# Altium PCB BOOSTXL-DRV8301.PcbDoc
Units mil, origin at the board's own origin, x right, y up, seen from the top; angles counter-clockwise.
Board outline 2200 x 2300 mil, 2 copper layers (Top, Bottom), stack 61.9 mil thick; 114 components, 81 nets, 348 pads, 370 vias.
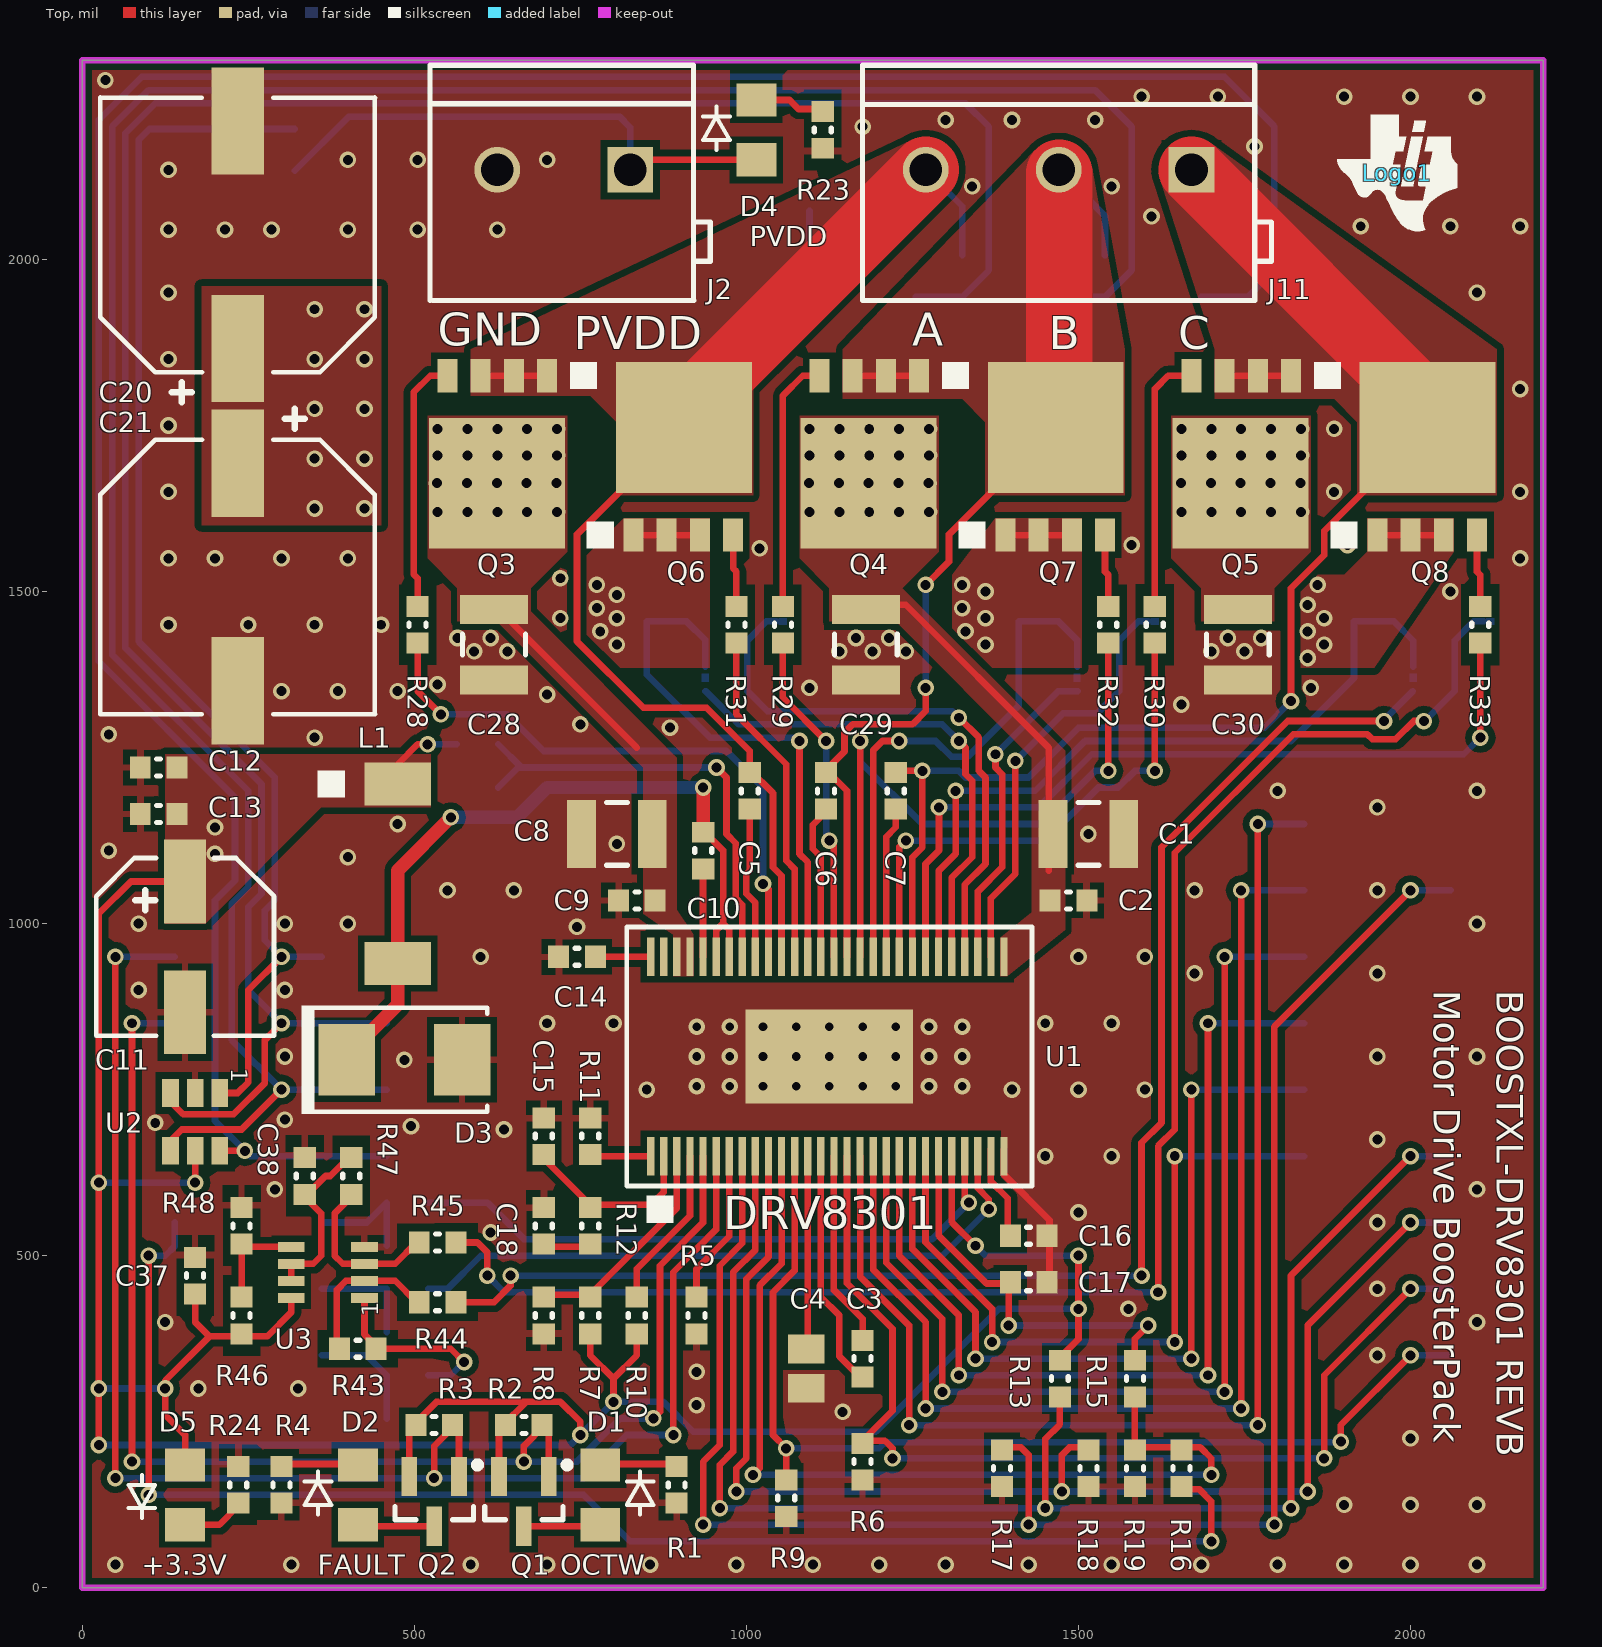
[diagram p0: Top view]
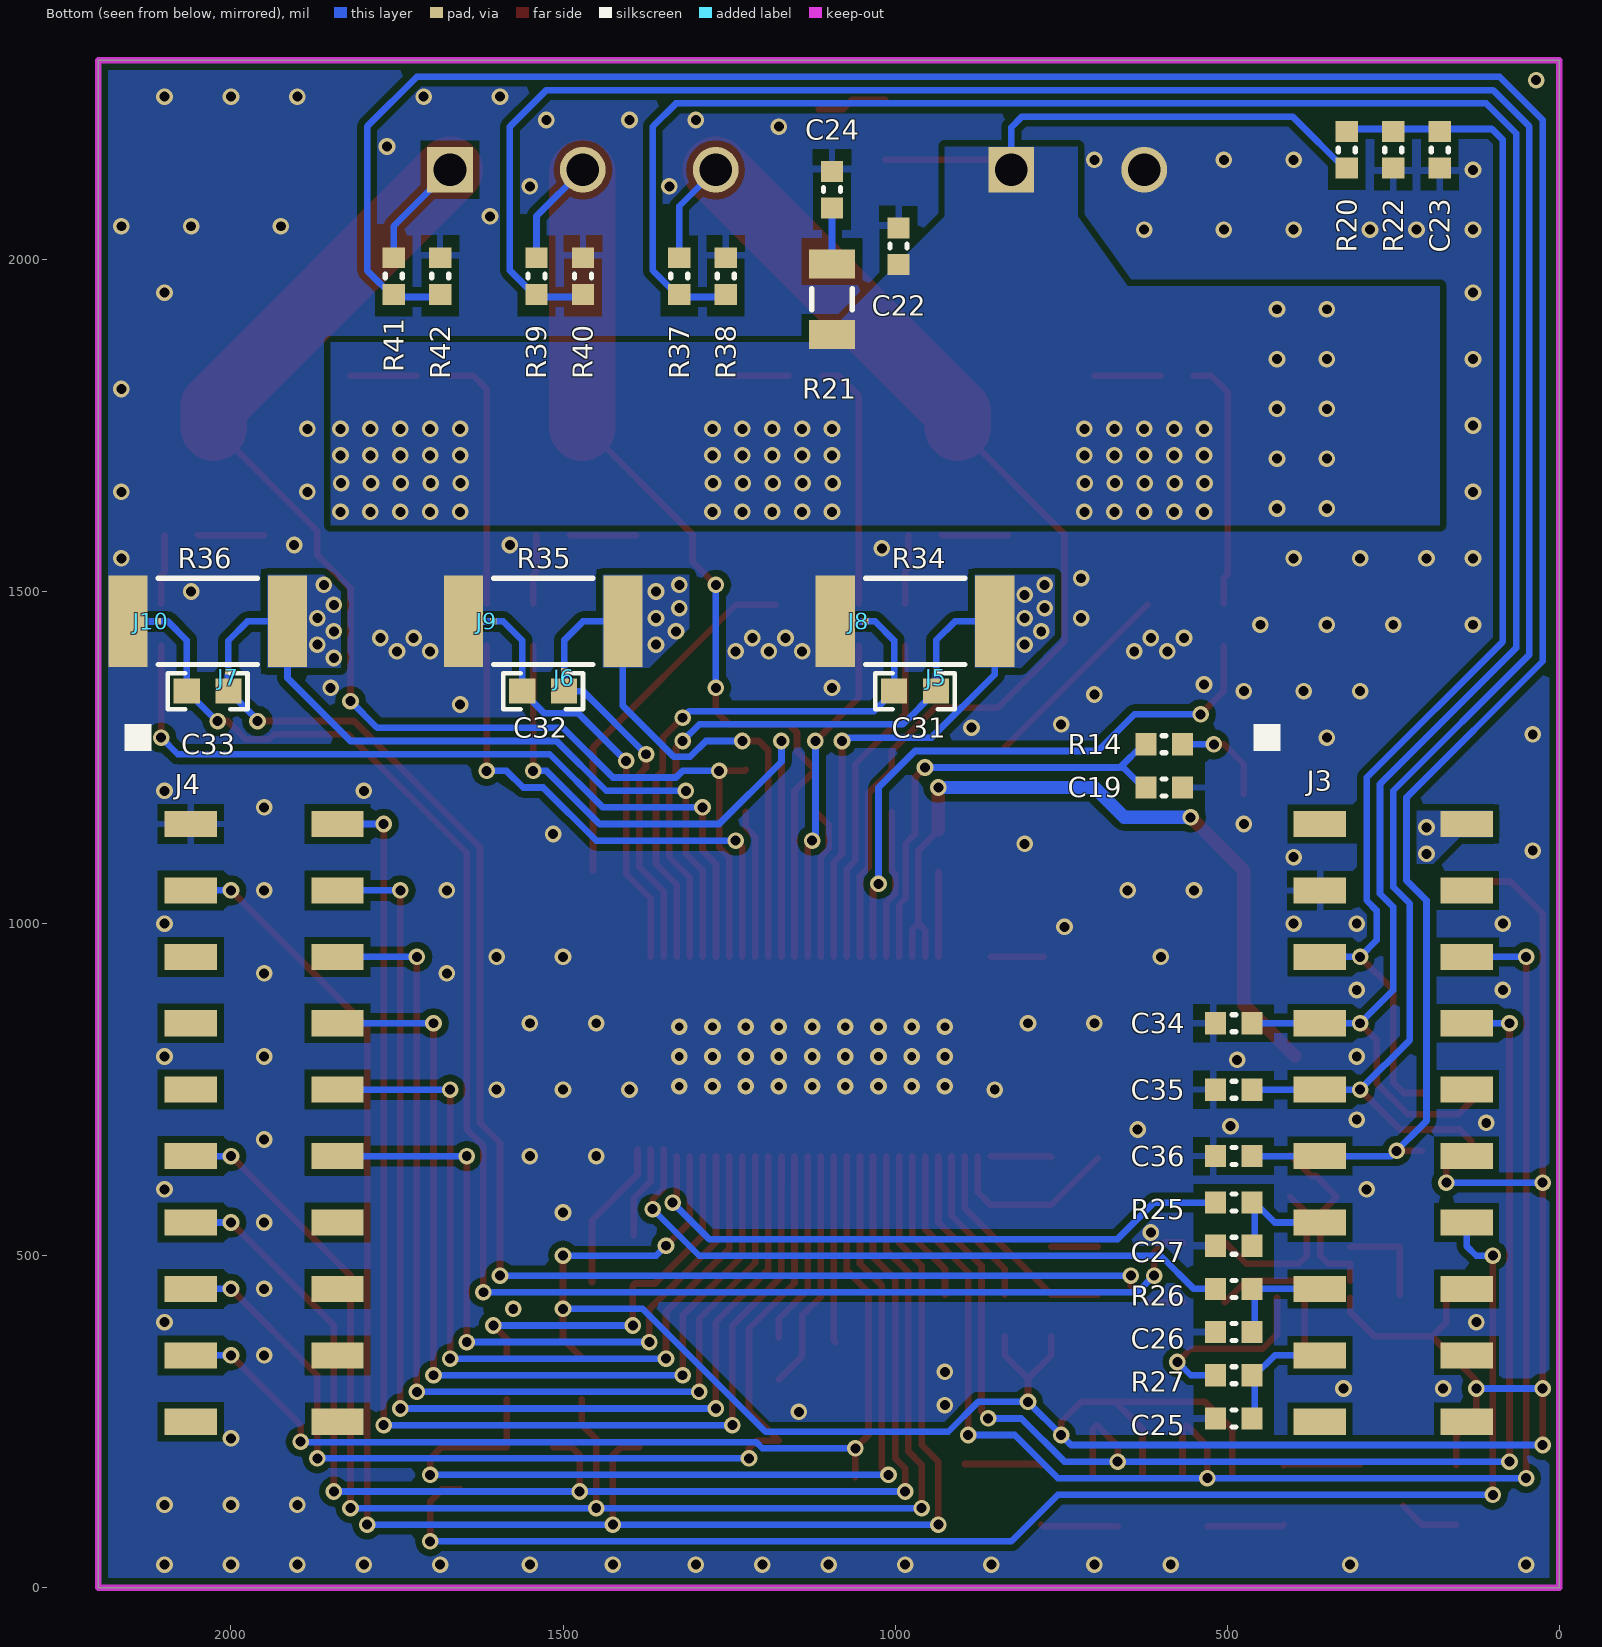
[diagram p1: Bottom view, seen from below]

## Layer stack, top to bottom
Top: signal copper 1.35
Dielectric: core 59.2, FR-4, Dk 4.3
Bottom: signal copper 1.35

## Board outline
0,0 0,2300 2200,2300 2200,0

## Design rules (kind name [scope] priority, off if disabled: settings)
Clearance Clearance_Poly_GND [InNamedPolygon('GND_TOP') or InNamedPolygon('GND_BOT')] p1: gap=10
Clearance "'Default' PADS rule_18" [All] p2: gap=6
Clearance "'Default' PADS rule_15" [IsVia vs IsVia] p3: gap=6
ComponentClearance "'Default' PADS rule_12" [All] p1: gap=0 collisioncheckmode=3 verticalgap=0 showdistances=FALSE
DiffPairsRouting [All] p1: maxlimit=10 minlimit=10 mostfreqgap=10 maxuncoupledlength=500
FlightTimeFalling "'Default' PADS rule_10" [All] p1: maximum=10.00
FlightTimeRising "'Default' PADS rule_9" [All] p1: maximum=10.00
MaxMinImpedance "'Default' PADS rule_8" [All] p1: minimum=50.00 maximum=150.0
MinimumSolderMaskSliver [All] p1: minsoldermaskwidth=4
PlaneClearance "'Default' PADS rule_14" [All] p1: clearance=15
PolygonConnect PolygonConnect_1 [IsNamedPolygon('GND_Top') or IsNamedPolygon('GND_Bot') vs Not (InComponent('U1') or InComponent('J2') or InComponent('J11') or InComponent('J1') or InComponent('J5') or InComponent('J6') or InComponent('J7') or InComponent('J8') or InComponent('J9') or InComponent('J10') or InComponent('C1') or InComponent('C4') or InComponent('C8') or InComponent('C16') or InComponent('C17') or InComponent('C20') or InComponent('C21') or InComponent('C28') or InComponent('C29') or InComponent('C30') or InComponent('R34') or InComponent('R35') or InComponent('R36') or IsStitchingVia or IsVia)] p1: connectstyle=Relief reliefconductorwidth=10 reliefentries=4 polygonreliefangle="90 Angle" airgapwidth=10
PolygonConnect [All] p2: connectstyle=Direct reliefconductorwidth=10 reliefentries=4 polygonreliefangle="90 Angle" airgapwidth=10
RoutingLayers "'Default' PADS rule_3" [All] p1: top layer_v5=TRUE bottom layer_v5=TRUE
RoutingPriority "'Default' PADS rule_2" [All] p1: routingpriority=3
RoutingTopology "'Default' PADS rule" [All] p1: topology=Shortest
RoutingVias "'Default' PADS rule_4" [All] p1: holewidth=15 width=25 viastyle="Through Hole" minholewidth=10 minwidth=15 maxholewidth=25 maxwidth=60
SMDToCorner "'Default' PADS rule_16" [All] p1: distance=0
SMDToPlane "'Default' PADS rule_17" [All] p1: distance=80000
SilkToSilkClearance [All] p1: silktosilkclearance=5
SilkscreenOverComponentPads [All] p1: minsilkscreentomaskgap=3
SolderMaskExpansion "Solder Mask Expansion from CAM settings" [All] p1: expansion=2
Width "'Default' PADS rule_13" [All] p1: maxlimit=150 minlimit=10 preferedwidth=10
19 further rules are at their usual default settings.

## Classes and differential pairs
component class DRV8301: C1 C2 C3 C4 C5 C6 C7 C8 C9 C10 C11 C12 C13 C14 C15 C16 C17 C18 C19 D1 D2 D3 L1 Logo1 Q1 Q2 R1 R2 R3 R4 R5 R6 R7 R8 R9 R10 R11 R12 R13 R14 R15 R16 R17 R18 R19 U1
component class LAUNCHPAD: C20 C21 C22 C23 C24 C25 C26 C27 D4 D5 J2 J3 J4 R20 R21 R22 R23 R24 R25 R26 R27 U2
component class MOTOR: C28 C29 C30 C31 C32 C33 J5 J6 J7 J8 J9 J10 J11 Q3 Q4 Q5 Q6 Q7 Q8 R28 R29 R30 R31 R32 R33 R34 R35 R36
component class SENSE: C34 C35 C36 C37 C38 R37 R38 R39 R40 R41 R42 R43 R44 R45 R46 R47 R48 U3
differential pair C_ISENSE: +C_ISENSE_P -C_ISENSE_N
differential pair A_ISENSE: +A_ISENSE_P -A_ISENSE_N
differential pair B_ISENSE: +B_ISENSE_P -B_ISENSE_N

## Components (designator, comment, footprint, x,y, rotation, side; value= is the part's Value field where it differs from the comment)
C1 "GRM32ER72A225KA35L" 1210L 1515,1135 r0 top
C2 "GRM188R72A104KA35D" 0603L 1485,1035 r0 top
C3 "C1608X7R1H223K" 0603L 1175,345 r90 top
C4 "GRM219R61E225KA12D" 0805L 1090,330 r270 top
C5 "C1608X7R1H104K" 0603L 1005,1200 r90 top
C6 "C1608X7R1H104K" 0603L 1120,1200 r90 top
C7 "C1608X7R1H104K" 0603L 1225,1200 r90 top
C8 "GRM32ER72A225KA35L" 1210L 805,1135 r180 top
C9 "GRM188R72A104KA35D" 0603L 835,1035 r180 top
C10 "C1608X7R1H104K" 0603L 935,1110 r270 top
C11 "EEE-FK1E470P" SM_RADIAL_D 155,965 r270 top
C12 "C1608X7R1E104K" 0603L 115,1235 r180 top
C13 "C1608X5R1E105K080AC" 0603L 115,1165 r180 top
C14 "GRM188R71H153KA01D" 0603L 745,950 r180 top
C15 "GRM1885C1H121JA01D" 0603L 695,680 r90 top
C16 "GRM188R61E105KA12D" 0603L 1425,530 r0 top
C17 "GRM188R61E105KA12D" 0603L 1425,460 r0 top
C18 "GRM188R71H682KA01D" 0603L 695,545 r90 top
C19 "C1608X7R1E104K" 0603L 595,1205 r180 bottom
C20 "EEE-FC1H221P" SM_RADIAL_G 234,2037 r90 top
C21 "EEE-FC1H221P" SM_RADIAL_G 234,1522 r270 top
C22 "GRM188R72A104KA35D" 0603L 995,2020 r90 bottom
C23 "C0603C104J4RACTU" 0603L 180,2165 r270 bottom
C24 "C1608X7R2A103K" 0603L 1095,2105 r90 bottom
C25 "GRM188R71C222KA01D" 0603L 490,255 r0 bottom
C26 "GRM188R71C222KA01D" 0603L 490,385 r0 bottom
C27 "GRM188R71C222KA01D" 0603L 490,515 r0 bottom
C28 "GRM32ER72A225KA35L" 1210L 620,1420 r270 top
C29 "GRM32ER72A225KA35L" 1210L 1180,1420 r270 top
C30 "GRM32ER72A225KA35L" 1210L 1740,1420 r270 top
C31 "C0603C102J5GAC" 0603 970,1350 r0 bottom
C32 "C0603C102J5GAC" 0603 1530,1350 r0 bottom
C33 "C0603C102J5GAC" 0603 2035,1350 r0 bottom
C34 "C0603C104J4RACTU" 0603L 490,850 r0 bottom
C35 "C0603C104J4RACTU" 0603L 490,750 r0 bottom
C36 "C0603C104J4RACTU" 0603L 490,650 r0 bottom
C37 "C0603C104J4RACTU" 0603L 170,470 r90 top
C38 "C0603C225M8PACTU" 0603L 335,620 r90 top
D1 "D-LED_0805" LED_0805 780,140 r270 top
D2 "D-LED_0805" LED_0805 415,140 r270 top
D3 "CDBB2100-G" SMB 485,795 r0 top
D4 "D-LED_0805" LED_0805 1015,2195 r270 top
D5 "D-LED_0805" LED_0805 155,140 r90 top
J2 "TERM_BLK_2PIN" CONN_ED120-2DS 725,2135 r90 top
J3 "HEADER_NPTC202KFM" HEADER_NPTC202KFM 250,700 r270 bottom
J4 "HEADER_NPTC202KFM" HEADER_NPTC202KFM 1950,700 r270 bottom
J5 "Net-Tie" Net-Tie_10mil 938,1370 r270 bottom net-tie
J6 "Net-Tie" Net-Tie_10mil 1498,1370 r270 bottom net-tie
J7 "Net-Tie" Net-Tie_10mil 2004,1370 r270 bottom net-tie
J8 "Net-Tie" Net-Tie_10mil 1055,1455 r180 bottom net-tie
J9 "Net-Tie" Net-Tie_10mil 1615,1455 r180 bottom net-tie
J10 "Net-Tie" Net-Tie_10mil 2120,1455 r180 bottom net-tie
J11 "TERM_BLK_3PIN" CONN_ED120_3DS 1470.2,2135 r270 top
L1 "DR74-330-R" IND_DR74 475,1075 r0 top
Logo1 "Texas Instruments" TI_Symbol_Overlay_Small 1980,2130 r0 top
Q1 "TR_PFET_SOT23" SOT-23 665,130 r270 top
Q2 "TR_PFET_SOT23" SOT-23 530,130 r270 top
Q3 "TR-CSD18533Q5A" QFN5X6MM 625,1710 r180 top
Q4 "TR-CSD18533Q5A" QFN5X6MM 1185,1710 r180 top
Q5 "TR-CSD18533Q5A" QFN5X6MM 1745,1710 r180 top
Q6 "TR-CSD18533Q5A" QFN5X6MM 905,1700 r0 top
Q7 "TR-CSD18533Q5A" QFN5X6MM 1465,1700 r0 top
Q8 "TR-CSD18533Q5A" QFN5X6MM 2025,1700 r0 top
R1 "CRCW0603330RJNEA" 0603L 895,155 r90 top
R2 "CRCW060310K0JNEA" 0603L 665,245 r180 top
R3 "CRCW060310K0JNEA" 0603L 530,245 r180 top
R4 "CRCW0603330RJNEA" 0603L 300,155 r90 top
R5 "CRCW06031R00JNEA" 0603L 925,410 r90 top
R6 "CRCW06031K00JNEA" 0603L 1175,190 r90 top
R7 "CRCW060331K6FKEA" 0603L 765,410 r270 top
R8 "RG1608P-103-B-T5" 0603L 695,410 r90 top
R9 "CRCW06031K00JNEA" 0603L 1060,135 r90 top
R10 "CRCW060310K0JNEA" 0603L 835,410 r270 top
R11 "CRCW0603205KFKEA" 0603L 765,680 r270 top
R12 "CRCW060316K2FKEA" 0603L 765,545 r90 top
R13 "CRCW060310K0JNEA" 0603L 1472,315 r90 top
R14 "CRCW06030000Z0EA" 0603L 595,1270 r180 bottom
R15 "CRCW0603100KJNEA" 0603L 1585,315 r270 top
R16 "CRCW06030000Z0EA" 0603L 1655,180 r90 top
R17 "CRCW060310K0JNEA" 0603L 1385,180 r90 top
R18 "CRCW060310K0JNEA" 0603L 1515,180 r90 top
R19 "CRCW06033K00JNEA" 0603L 1585,180 r90 top
R20 "CRCW060334K8FKEA" 0603L 320,2165 r270 bottom
R21 "CRCW12063R30JNEA" 1206L 1095,1940 r270 bottom
R22 "CRCW06034K99FKEA" 0603L 250,2165 r90 bottom
R23 "CRCW06034K99FKEA" 0603L 1115,2195 r90 top
R24 "CRCW0603330RJNEA" 0603L 235,155 r270 top
R25 "CRCW060356R0JNEA" 0603L 490,580 r0 bottom
R26 "CRCW060356R0JNEA" 0603L 490,450 r0 bottom
R27 "CRCW060356R0JNEA" 0603L 490,320 r0 bottom
R28 "CRCW060310R0JNEA" 0603L 505,1450 r90 top
R29 "CRCW060310R0JNEA" 0603L 1055,1450 r90 top
R30 "CRCW060310R0JNEA" 0603L 1615,1450 r90 top
R31 "CRCW060310R0JNEA" 0603L 985,1450 r90 top
R32 "CRCW060310R0JNEA" 0603L 1545,1450 r90 top
R33 "CRCW060310R0JNEA" 0603L 2105,1450 r90 top
R34 "CRA2512-FZ-R010ELF" 2512M 970,1455 r180 bottom
R35 "CRA2512-FZ-R010ELF" 2512M 1530,1455 r180 bottom
R36 "CRA2512-FZ-R010ELF" 2512M 2035,1455 r180 bottom
R37 "CRCW060334K8FKEA" 0603L 1325,1975 r270 bottom
R38 "CRCW06034K99FKEA" 0603L 1255,1975 r270 bottom
R39 "CRCW060334K8FKEA" 0603L 1540,1975 r270 bottom
R40 "CRCW06034K99FKEA" 0603L 1470,1975 r270 bottom
R41 "CRCW060334K8FKEA" 0603L 1755,1975 r270 bottom
R42 "CRCW06034K99FKEA" 0603L 1685,1975 r270 bottom
R43 "RG1608P-103-B-T5" 0603L 415,360 r0 top
R44 "CRCW06031K00FKEA" 0603L 535,430 r180 top
R45 "CRCW06031K00FKEA" 0603L 535,520 r180 top
R46 "RG1608P-103-B-T5" 0603L 240,410 r270 top
R47 "CRCW060310K0JNEA" 0603L 405,620 r270 top
R48 "RG1608P-103-B-T5" 0603L 240,545 r270 top
U1 "DRV8301DCA" DCA_56P 1125,800 r90 top
U2 "NUP4201MR6" SOT23-6 170,700 r270 top
U3 "OPA2374AIDCN" DCN 370,475 r180 top

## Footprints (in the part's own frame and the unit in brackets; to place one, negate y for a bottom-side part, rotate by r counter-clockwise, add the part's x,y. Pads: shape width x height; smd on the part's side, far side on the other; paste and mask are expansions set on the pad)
0603 [mm] "0603 from SM-752 data"
  rect 1x0.95 smd: 1(-0.8,0) 2(0.8,0)
  silkscreen extent -1.52,-0.69 1.52,0.69, body extent -0.87,-0.47 0.87,0.47, height 0.85
0603L [mm] "0603 from SM-752 data"
  rect 0.8x0.85 smd: 1(-0.7,0) 2(0.7,0)
  silkscreen extent -0.07,-0.33 0.07,0.33, body extent -0.87,-0.47 0.87,0.47, height 0.85
0805L [mm] "0805 from SM-752 data"
  rect 1.1x1.4 smd: 1(-0.75,0) 2(0.75,0)
  body extent -1.1,-0.72 1.1,0.72, height 1.1
1206L [mm] "1206 from SM-752 data"
  rect 1.1x1.75 smd: 1(-1.35,0) 2(1.35,0)
  silkscreen extent -0.4,-0.77 0.4,0.77, body extent -1.7,-0.9 1.7,0.9, height 1.35
1210L [mm] "1210 from SM-752 data"
  rect 1.1x2.6 smd: 1(-1.35,0) 2(1.35,0)
  silkscreen extent -0.4,-1.2 0.4,1.2, body extent -1.7,-1.35 1.7,1.35, height 1.35
2512M [mm] "Chip Resistor, Body 6.3x3.2mm, IPC Low Density"
  rect 1.5x3.5 smd: 1(-3.05,0) 2(3.05,0)
  silkscreen extent -1.9,-1.65 1.9,1.65, body extent -3.22,-1.67 3.22,1.67, height 0.71
CONN_ED120-2DS [mm] "ONSHORE"
  rect 1.75x1.75 hole 1.25: 1(0,-2.54)
  round 1.75 hole 1.25: 2(0,2.54)
  silkscreen extent -5,-5.6 4,5.12, body extent -5,-5.6 4.15,5.12, height 13.1
CONN_ED120_3DS [mm] "ONSHORE"
  rect 1.75x1.75 hole 1.25: 1(0,5.08)
  round 1.75 hole 1.25: 2(0,0) 3(0,-5.08)
  silkscreen extent -4,-7.5 5,8.14, body extent -4.13,-7.55 5.05,8.14, height 13.1
DCA_56P [mil]
  rect 58x11 smd mask+2: 1(-150.08,268.98) 2(-150.08,249.3) 3(-150.08,229.61) 4(-150.08,209.91) 5(-150.08,190.21) 6(-150.08,170.51) 7(-150.08,150.81) 8(-150.08,131.11) 9(-150.08,111.41) 10(-150.08,91.71) 11(-150.08,72.01) 12(-150.08,52.31) 13(-150.08,32.61) 14(-150.08,12.91) 15(-150.08,-6.79) 16(-150.08,-26.49) 17(-150.08,-46.19) 18(-150.08,-65.89) 19(-150.08,-85.59) 20(-150.08,-105.29) 21(-150.08,-124.99) 22(-150.08,-144.69) 23(-150.08,-164.39) 24(-150.08,-184.09) 25(-150.08,-203.79) 26(-150.08,-223.49) 27(-150.08,-243.17) 28(-150.08,-262.86) 29(149.92,-262.86) 30(149.92,-243.17) 31(149.92,-223.49) 32(149.92,-203.79) 33(149.92,-184.09) 34(149.92,-164.39) 35(149.92,-144.69) 36(149.92,-124.99) 37(149.92,-105.29) 38(149.92,-85.59) 39(149.92,-65.89) 40(149.92,-46.19) 41(149.92,-26.49) 42(149.92,-6.79) 43(149.92,12.91) 44(149.92,32.61) 45(149.92,52.31) 46(149.92,72.01) 47(149.92,91.71) 48(149.92,111.41) 49(149.92,131.11) 50(149.92,150.81) 51(149.92,170.51) 52(149.92,190.21) 53(149.92,209.91) 54(149.92,229.61) 55(149.92,249.3) 56(149.92,268.98)
  rect 141.73x251.97 smd: 57(0.02,0.01)
  silkscreen extent -250,235 -210,275
DCN [mil]
  rect 40x15 smd: 1(-55,38.4) 2(-55,12.8) 3(-55,-12.8) 4(-55,-38.4) 5(55,-38.4) 6(55,-12.8) 7(55,12.8) 8(55,38.4)
HEADER_NPTC202KFM [mm]
  rect 1x2 smd paste+0.033 mask+0.041: 1(-11.43,-2.807) 2(-11.43,2.807) 3(-8.89,-2.807) 4(-8.89,2.807) 5(-6.35,-2.807) 6(-6.35,2.807) 7(-3.81,-2.807) 8(-3.81,2.807) 9(-1.27,-2.807) 10(-1.27,2.807) 11(1.27,-2.807) 12(1.27,2.807) 13(3.81,-2.807) 14(3.81,2.807) 15(6.35,-2.807) 16(6.35,2.807) 17(8.89,-2.807) 18(8.89,2.807) 19(11.43,-2.807) 20(11.43,2.807)
  silkscreen extent -15.24,-5.33 -14.22,-4.32
IND_DR74 [mil]
  rect 100x65 smd: 1(0,135) 2(0,-135)
  silkscreen extent -120,115 -80,155
LED_0805 [mil]
  rect 50x60 smd: 1(-45,0) 2(45,0)
  silkscreen extent -35,40 30,80
Net-Tie_10mil [mil] "10mil net tie, no solder mask opening, no solder paste"
  rect 10x10 smd paste-5 mask-5: 1(-10,0) 2(10,0)
  Top region: -6,5 6,5 6,-5 -6,-5
QFN5X6MM [mil]
  rect 30x50 smd paste+1.5 mask+1.5: 1(-75,-115) 2(-25,-115) 3(25,-115) 4(75,-115)
  rect 204.72x196.85 smd paste+0.64 mask+0.64: 5(0.79,46.85)
  silkscreen extent -150,-135 -110,-95
SM_RADIAL_D [mm] "6.3 x 5.8mm:  Panasonic D"
  rect 3.2x1.6 smd: 1(-2.5,0) 2(2.5,0)
  silkscreen extent -3.4,-3.4 3.4,3.4, body extent -3.41,-3.41 3.41,3.41, height 6.1
SM_RADIAL_G [mm] "10 x 10.2mm:  Panasonic G"
  rect 4.1x2 smd: 1(-4.35,0) 2(4.35,0)
  silkscreen extent -5.25,-5.25 5.25,5.25, body extent -5.26,-5.26 5.26,5.26, height 10.5
SMB [mil] "Molded Diode, 2-Leads, Body 5.4x3.6mm, IPC Medium Density, based on OnSemi component dimensions"
  rect 85x107.99 smd: 1(-87.01,0) 2(87.01,0)
  silkscreen extent -155,-82 125,82, body extent -106,-71 106,71, height 91
SOT23-6 [mil]
  rect 42x25 smd: 1(-45,37) 2(-45,0) 3(-45,-37) 4(42,-37) 5(42,0) 6(42,37)
SOT-23 [mm] "SOT23, 3-Leads, Body 2.9x1.3mm, Pitch 0.95mm, Lead Span 2.5mm, IPC Medium Density"
  rect 1.5x0.6 smd: 1(-0.95,0.95) 2(-0.95,-0.95) 3(0.95,0)
  silkscreen extent -1.52,-1.5 0.7,1.78, body extent -1.16,-1.45 1.21,1.45, height 1
TI_Symbol_Overlay_Small [mil]
  silkscreen extent -90,-88 91,88

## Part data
C1 C8 C28 C29 C30: "CAP, CERM, 2.2uF, 100V, +/-10%, X7R, 1210"
C2 C9 C22: "CAP, CERM, 0.1uF, 100V, +/-10%, X7R, 0603"
C3: "CAP, CERM, 0.022uF, 50V, +/-10%, X7R, 0603"
C4: "CAP, CERM, 2.2uF, 25V, +/-10%, X5R, 0805"
C5 C6 C7 C10: "CAP, CERM, 0.1uF, 50V, +/-10%, X7R, 0603"
C11: "CAP, AL, 47uF, 25V, +/-20%, 0.36 ohm, SMD"
C12 C19: "CAP, CERM, 0.1uF, 25V, +/-10%, X7R, 0603"
C13 C16 C17: "CAP, CERM, 1uF, 25V, +/-10%, X5R, 0603"
C14: "CAP, CERM, 0.015uF, 50V, +/-10%, X7R, 0603"
C15: "CAP, CERM, 120pF, 50V, +/-5%, C0G/NP0, 0603"
C18: "CAP, CERM, 6800pF, 50V, +/-10%, X7R, 0603"
C20 C21: "CAP, AL, 220uF, 50V, +/-20%, 0.3 ohm, SMD"
C23 C34 C35 C36 C37: "CAP, CERM, 0.1uF, 16V, +/-5%, X7R, 0603"
C24: "CAP, CERM, 0.01uF, 100V, +/-10%, X7R, 0603"
C25 C26 C27: "CAP, CERM, 2200pF, 16V, +/-10%, X7R, 0603"
C31 C32 C33: "CAP, CERM, 1000pF, 50V, +/-5%, C0G/NP0, 0603"
C38: "CAP, CERM, 2.2uF, 10V, +/-20%, X5R, 0603"
D1: "LED THIN 585NM YEL DIFF 0805 SMD"
D2: "LED THIN660NM SUPRED DIFF0805SMD"
D3: library part CDBC5100-G, "Diode, Schottky, 100V, 2A, SMB"
D4 D5: "LED THIN 565NM GRN DIFF 0805 SMD"
J2: library part ED120/2DS, "TERMINAL BLOCK 5.08MM VERT 2POS"
J3 J4: "CONN RCPT 20POS .100 DL STR SMD"
J5 J6 J7 J8 J9 J10: "Single point connection between nets."
J11: library part ED120/3DS, "TERMINAL BLOCK 5.08MM VERT 3POS"
L1: library part IND_DR74-XXX, "INDUCTOR SHIELD PWR 33UH SMD"
Logo1: library part TI_Logo, "Texas Instrument Corporate Signature"
Q1 Q2: "MOSFET P-CH 8V 5.4A SOT23-3"
Q3 Q4 Q5 Q6 Q7 Q8: "MOSFET, N-Chan, 60V, 18A, 6.1 mOhm"
R1 R4 R24: "RES, 330 ohm, 5%, 0.1W, 0603"
R2 R3 R10 R13 R17 R18 R47: "RES, 10k ohm, 5%, 0.1W, 0603"
R5: "RES, 1.0 ohm, 5%, 0.1W, 0603"
R6 R9: "RES, 1.0k ohm, 5%, 0.1W, 0603"
R7: "RES, 31.6k ohm, 1%, 0.1W, 0603"
R8 R43 R46 R48: "RES, 10.0k ohm, 0.1%, 0.1W, 0603"
R11: "RES, 205k ohm, 1%, 0.1W, 0603"
R12: "RES, 16.2k ohm, 1%, 0.1W, 0603"
R14 R16: "RES, 0 ohm, 5%, 0.1W, 0603"
R15: "RES, 100k ohm, 5%, 0.1W, 0603"
R19: "RES, 3.0k ohm, 5%, 0.1W, 0603"
R20 R37 R39 R41: "RES, 34.8k ohm, 1%, 0.1W, 0603"
R21: "RES, 3.3 ohm, 5%, 0.25W, 1206"
R22 R23 R38 R40 R42: "RES, 4.99k ohm, 1%, 0.1W, 0603"
R25 R26 R27: "RES, 56 ohm, 5%, 0.1W, 0603"
R28 R29 R30 R31 R32 R33: "RES, 10 ohm, 5%, 0.1W, 0603"
R34 R35 R36: "RES, 0.01 ohm, 1%, 3W, 2512"
R44 R45: "RES, 1.00k ohm, 1%, 0.1W, 0603"
U1: library part DRV8302DCA_ERIC, "IC, 3 Phase Pre-Driver with Dual Current Shunt Amplifiers and Buck Regulator-Hardware Controlled"
U2: "IC,  500w 6v, Transient Voltage  Suppressors"
U3: "IC, CMOS, R-R I/O  Op Amp, Single Supply, 6.5MHz, 585uA"

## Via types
v1: diameter 25, hole 15, Top to Bottom, tented both sides, 343 vias
v2: diameter 25, hole 13, Top to Bottom, tented both sides, 27 vias

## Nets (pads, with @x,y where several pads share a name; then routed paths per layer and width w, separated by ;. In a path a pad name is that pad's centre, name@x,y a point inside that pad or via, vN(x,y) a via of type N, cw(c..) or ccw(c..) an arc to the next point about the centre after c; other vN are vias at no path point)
+3.3V: C11.1 C12.1 C13.1 C37.1 D5.2 J3.2 L1.1 Q1.2 Q2.2 R2.2 R3.2 R7.2 R10.2 R13.2 R14.2 R46.2 U1.24 U2.5 U3.8 | length 4623.9
  Top w10: v1(25,215) v1(25,300) v1(25,610) 25,1015 73.43,1063.43 C11.1 ; D5.2 155,230 125,260 v1(125,300) 125,312.01 191.5,378.5 ; C37.1@170,438.5 170,400 191.5,378.5 ; v1(170,610) U2.5 ; U3.8 315,415 278.5,378.5 240,378.5 191.5,378.5 ; L1.1@475,1195 475,1240 505,1270 v1(520,1270) ; Q2.2 492.6,239.09 498.5,245 533.5,280 668.5,280 ; Q1.2 627.6,239.09 633.5,245 668.5,280 ; v1(750,230) 750,250 720,280 668.5,280 ; R7.2@765,378.5 765,350 800,315 ; v1(800,280) 800,315 ; R10.2@835,378.5 835,350 800,315 ; U1.24 1309.09,550.91 v1(1345,515) ; R13.2@1472,346.5 1500,374.5 v1(1500,420) v1(1500,500)
  Bottom w10: v1(25,215) 735,215 v1(750,230) v1(800,280) 875,280 920,235 1195,235 1380,420 v1(1500,420) ; v1(25,300) v1(125,300) ; v1(25,610) v1(170,610) ; v1(520,1270) R14.2@563.5,1270 ; v1(1345,515) 1360,500 v1(1500,500)
  other v1: 200,1105 200,1145
+PVDD: C1.1 C2.1 C8.1 C9.1 C20.1 C21.1 C22.1 C28.1 C29.1 C30.1 D4.2 J2.1 Q3.5 Q4.5 Q5.5 R20.2 R21.2 U1.29 U1.53 U1.54 | length 1658.7
  Top w10: C28.1@620,1480 621.46,1478.54 835,1265 ; J2.1 840,2150 D4.2 ; C29.1@1180,1480 1240,1480 1455,1265 1455,1095 1455,1080
  Bottom w10: R20.2@320,2133.5 401.5,2215 809,2215 825,2199 J2.1
  other v1: 535,1620 580,1620 625,1620 670,1620 715,1620 1095,1620 1140,1620 1185,1620 1230,1620 1275,1620 1655,1620 1700,1620 1745,1620 1790,1620 1835,1620 350,1625 425,1625 534.21,1663.15 579.21,1663.15 624.21,1663.15 669.21,1663.15 714.21,1663.15 1094.21,1663.15 1139.21,1663.15 1184.21,1663.15 1229.21,1663.15 1274.21,1663.15 1654.21,1663.15 1699.21,1663.15 1744.21,1663.15 1789.21,1663.15 1834.21,1663.15 350,1700 425,1700 535,1705 580,1705 625,1705 670,1705 715,1705 1095,1705 1140,1705 1185,1705 1230,1705 1275,1705 1655,1705 1700,1705 1745,1705 1790,1705 1835,1705 535,1745 580,1745 625,1745 670,1745 715,1745 1095,1745 1140,1745 1185,1745 1230,1745 1275,1745 1655,1745 1700,1745 1745,1745 1790,1745 1835,1745 350,1775 425,1775 350,1850 425,1850 350,1925 425,1925
\FAULT: J3.6 Q2.1 R3.1 U1.6 | length 2361.1
  Top w10: v1(50,165) v1(50,950) ; v1(530,165) 530,213.5 561.5,245 567.4,239.09 Q2.1 ; v1(890,230) 890,475 954.5,539.5 954.5,604.9 U1.6
  Bottom w10: v1(50,165) v1(530,165) 755,165 820,230 v1(890,230) ; v1(50,950) J3.6
\OCTW: J3.8 Q1.1 R2.1 U1.5 | length 2110.4
  Top w10: v1(75,190) v1(75,850) ; v1(665,190) 665,213.5 696.5,245 702.4,239.09 Q1.1 ; v1(860,255) 870,265 870,485 934.8,549.8 U1.5
  Bottom w10: v1(75,190) v1(665,190) 745,190 810,255 v1(860,255) ; v1(75,850) J3.8
A_ISENSE_N: C31.2 J8.2 U1.32 | length 856.5
  Top w10: v1(1320,1310) 1350,1280 1350,1230 1360,1220 1360,1090 1328.79,1058.79 U1.32
  Bottom w10: J8.2 1030,1455 1001.5,1426.5 C31.2 1031.5,1320 1310,1320 v1(1320,1310)
A_ISENSE_P: C31.1 J5.2 U1.33 | length 758.7
  Top w10: U1.33 1309.09,1069.09 1340,1100 1340,1215 1330,1225 1330,1265 v1(1320,1275)
  Bottom w10: C31.1 988.5,1300 1295,1300 v1(1320,1275)
B_ISENSE_N: C32.2 J9.2 U1.30 | length 642.1
  Top w10: U1.30 1368.17,1038.17 ; 1368.19,1038.19 1405,1075 v1(1405,1245)
  Bottom w10: v1(1405,1245) 1476.5,1316.5 1527.99,1316.5 C32.2 1561.5,1426.5 1590,1455 J9.2
B_ISENSE_P: C32.1 J6.2 U1.31 | length 487.2
  Top w10: U1.31 1348.49,1048.49 1385,1085 1385,1225 1375,1235 v1(1375,1255)
  Bottom w10: v1(1375,1255) 1470,1350 C32.1
BIAS/VDD_SPI: C19.1 R14.1 U1.49 | length 691.6
  Top w10: v1(955,1235) 970,1220 970,1135 984,1121 984,1038.37 993.89,1028.48 U1.49
  Bottom w10: C19.1@626.5,1205 656.5,1235 661.5,1235 ; R14.1@626.5,1270 661.5,1235 ; v1(955,1235) 661.5,1235
C_ISENSE_N: C33.2 J10.2 R45.1 | length 2437.4
  Top w10: R45.1@566.5,520 595,520 610,505 v1(610,470) ; v1(1620,445) 1620,665 1645,690 1645,1106.72 1823.28,1285 1935,1285 1942.5,1277.5 1977.5,1277.5 2005,1305 v1(2020,1305)
  Bottom w10: v1(610,470) 635,445 v1(1620,445) ; v1(2020,1305) 2021.5,1305 C33.2 2066.5,1426.5 2095,1455 J10.2
C_ISENSE_P: C33.1 J7.2 R44.1 | length 2188
  Top w10: R44.1@566.5,430 620,430 645,455 v1(645,470) ; v1(1595,470) 1595,670 1625,700 1625,1115 1815,1305 v1(1960,1305)
  Bottom w10: v1(645,470) v1(1595,470) ; v1(1960,1305) 1960,1306.5 C33.1
DC_CAL: J4.17 R9.2 U1.12 | length 1578.1
  Top w10: R9.2@1060,166.5 v1(1060,210) 1040,230 1040,445 1072.69,477.69 U1.12 ; v1(1895,220) 1895,245 v1(2000,350)
  Bottom w10: v1(1060,210) 1200,210 1209.31,219.31 v1@1895,219.31 ; v1(2000,350) J4.17
DC_V_FB: C23.1 J3.5 R20.1 R22.2 U2.1 | length 1893.2
  Top w10: U2.1 234,745 250,761 250,900 v1(300,950)
  Bottom w10: R20.1@320,2196.5 180,2196.5 101.5,2196.5 85,2180 85,1425 290,1220 290,1035 275,1020 275,975 v1(300,950) J3.5
DVDD: C17.1 R15.1 U1.23 | length 583
  Top w10: U1.23 1289.39,530.61 1361.75,458.25 1391.75,458.25 1395,455 v1(1395,395) ; R15.1@1585,346.5 1585,375 v1(1605,395)
  Bottom w10: v1(1395,395) v1(1605,395)
EN_GATE: J4.15 R6.2 U1.16 | length 1559.5
  Top w10: U1.16 1151.49,604.91 1151.5,458.5 1220,390 1220,266.5 1175,221.5 1208.5,221.5 1220,210 v1(1220,195) ; v1(1870,195) 1870,320 v1(2000,450)
  Bottom w10: v1(1220,195) v1(1870,195) ; v1(2000,450) J4.15
GAIN/SDO: J4.13 R18.2 U1.10 | length 2014.4
  Top w10: v1(985,145) 985,180 1000,195 1000,465 1033.3,498.3 1033.3,604.9 U1.10 ; v1(1475,145) 1475,200 1486.5,211.5 R18.2@1515,211.5 ; v1(1845,145) 1845,395 v1(2000,550)
  Bottom w10: v1(985,145) v1(1475,145) v1(1845,145) ; v1(2000,550) J4.13
GH_A: R28.1 U1.47 | length 895.4
  Top w10: R28.1@505,1418.5 505,1350 v1(540,1315) ; U1.47 v1@1033.29,1051.71
  Bottom w10: v1(540,1315) 640,1315 695,1260 970,1260 1025,1205 v1(1025,1060)
GH_B: R29.1 U1.42 | length 500.4
  Top w10: R29.1@1055,1418.5 1055,1340 v1(1120,1275) ; v1(1125,1125) 1131.79,1118.21 U1.42
  Bottom w10: v1(1120,1275) 1120,1130 v1(1125,1125)
GH_C: R30.1 U1.37 | length 772.4
  Top w10: U1.37 1230.29,1115.29 ; v1(1615,1230) R30.1@1615,1418.5
  Bottom w10: v1(1240,1125) 1450,1125 1530,1205 1560,1205 1585,1230 v1(1615,1230)
GL_A: R31.1 U1.45 | length 504.9
  Top w10: R31.1@985,1418.5 985,1315 1060,1240 1060,1095 1072.69,1082.31 U1.45
GL_B: R32.1 U1.40 | length 990.6
  Top w10: U1.40 v1(1171.19,1275) ; v1(1545,1230) R32.1@1545,1418.5
  Bottom w10: v1(1171.19,1275) 1171.19,1243.81 1265,1150 1445,1150 1525,1230 v1(1545,1230)
GL_C: R33.1 U1.35 | length 1230.5
  Top w10: U1.35 1269.69,1089.69 1290,1110 v1(1290,1175) ; v1(2105,1280) R33.1@2105,1418.5
  Bottom w10: v1(1290,1175) 1440,1175 1520,1255 2080,1255 v1(2105,1280)
GND: C1.2 C2.2 C4.2 C8.2 C9.2 C11.2 C12.2 C13.2 C14.2 C15.2 C16.2 C17.2 C18.2 C19.2 C20.2 C21.2 C22.2 C23.2 C24.2 C25.2 C26.2 C27.2 C28.2 C29.2 C30.2 C34.2 C35.2 C36.2 C37.2 C38.2 D3.2 J2.2 J3.3 J4.1 J8.1 J9.1 J10.1 R1.1 R4.1 R5.1 R6.1 R8.1 R9.1 R11.1 R17.1 R18.1 R19.1 R22.1 R23.1 R24.1 R34.1 R35.1 R36.1 R38.1 R40.1 R42.1 R48.1 U1.28 U1.57 U2.2 U3.4 | length 228.3
  Top w10: U1.28@1387.86,659.92 1387.86,622.14 1456.5,553.5 1456.5,530 C17.2@1456.5,460
  other v1: 50,35 315,35 585,35 700,35 855,35 985,35 1100,35 1200,35 1300,35 1425,35 1550,35 1685,35 1800,35 1900,35 2000,35 2100,35 1900,125 2000,125 2100,125 2000,225 1145,265 925,275 175,300 325,300 925,325 1950,350 125,400 2100,400 1575,420 1950,450 615,535 1950,550 1500,565 290,600 2100,600 1450,650 1550,650 1950,675 635,690 495,695 110,700 305,705 850,750 1400,750 1500,750 1600,750 485,795 305,800 1950,800 2100,800 700,850 800,850 1450,850 1550,850 85,900 305,900 1675,925 1950,925 600,950 1500,950 1600,950 745,995 85,1000 305,1000 400,1000 2100,1000 550,1050 650,1050 1675,1050 1950,1050 400,1100 40,1110 805,1120 1515,1135 475,1150 1950,1175 1800,1200 2100,1200 350,1280 40,1285 885,1295 750,1300 1655,1330 700,1345 300,1350 385,1350 475,1350 1095,1355 1850,1355 535,1360 590,1410 640,1410 1140,1410 1190,1410 1240,1410 1700,1410 1750,1410 565,1430 615,1430 1165,1430 1215,1430 1725,1430 1775,1430 130,1450 250,1450 350,1450 450,1450 720,1460 2060,1500 720,1520 130,1550 200,1550 300,1550 400,1550 2165,1550 1020,1565 1580,1570 1905,1570 130,1650 1885,1650 2165,1650 1885,1745 130,1750 2165,1805 130,1850 130,1950 2100,1950 130,2045 215,2045 285,2045 400,2045 505,2045 625,2045 1925,2050 2060,2050 2165,2050 1610,2065 1340,2110 1550,2110 130,2135 400,2150 505,2150 700,2150 1765,2170 1175,2200 1300,2210 1400,2210 1525,2210 1595,2245 1710,2245 1900,2245 2000,2245 2100,2245 35,2270
  other v2: 925.01,754.98 975.01,754.98 1025.01,754.98 1075.01,754.98 1125,755 1175.01,754.98 1225.01,754.98 1275.01,754.98 1325.01,754.98 925.01,799.98 975.01,799.98 1025.01,799.98 1075.01,799.98 1125,800 1175.01,799.98 1225.01,799.98 1275.01,799.98 1325.01,799.98 925.01,844.98 975.01,844.98 1025.01,844.98 1075.01,844.98 1125,845 1175.01,844.98 1225.01,844.98 1275.01,844.98 1325.01,844.98
IA_FB: R25.2 U1.25 | length 931.6
  Top w10: U1.25 1328.79,586.21 v1(1335,580)
  Bottom w10: R25.2@521.5,580 610,580 665,525 1280,525 v1(1335,580)
IB_FB: R26.2 U1.26 | length 990
  Top w10: U1.26@1348.49,659.92 1348.49,601.51 1365,585 v1(1365,570)
  Bottom w10: R26.2@521.5,450 550,450 600,500 1295,500 v1(1365,570)
M_OC/SDI: J4.11 R13.1 U1.9 | length 2249.8
  Top w10: v1(960,120) 960,185 980,205 980,475 1013.6,508.6 1013.6,604.9 U1.9 ; v1(1450,120) 1450,224 1472,246 R13.1@1472,283.5 ; v1(1820,120) 1820,470 v1(2000,650)
  Bottom w10: v1(960,120) v1(1450,120) v1(1820,120) ; v1(2000,650) J4.11
M_PWM/\SCS: J4.3 R17.2 U1.8 | length 2689.5
  Top w10: v1(935,95) 935,190 960,215 960,485 993.9,518.9 993.9,604.9 U1.8 ; R17.2@1385,211.5 1413.5,211.5 1425,200 v1(1425,95) ; v1(1795,95) 1795,845 v1(2000,1050)
  Bottom w10: v1(935,95) v1(1425,95) v1(1795,95) ; v1(2000,1050) J4.3
NetC3_1: C3.1 U1.14 | length 362.5
  Top w10: U1.14 1112.09,437.91 1140,410 1140,348.5 C3.1@1175,313.5
NetC3_2: C3.2 U1.15 | length 291.3
  Top w10: U1.15 1131.79,448.21 1175,405 C3.2@1175,376.5
NetC4_1: C4.1 U1.13 | length 280.9
  Top w10: C4.1@1090,370 1092.39,372.39 U1.13
NetC5_1: C5.1 U1.48 | length 226.3
  Top w10: C5.1@1005,1168.5 1005,1080 1000,1075 1000,1045 1013.59,1031.41 U1.48
NetC6_1: C6.1 U1.43 | length 231.9
  Top w10: U1.43 1112.09,1100.54 1100,1112.63 1100,1148.5 C6.1@1120,1168.5
NetC7_1: C7.1 U1.38 | length 224.6
  Top w10: U1.38 1210.59,1130.59 1225,1145 C7.1@1225,1168.5
NetC10_2: C10.2 U1.52 | length 128.4
  Top w10: U1.52 C10.2@934.79,1078.29
NetC14_1: C14.1 U1.56 | length 79.4
  Top w10: C14.1@776.58,949.92 U1.56
NetC15_1: C15.1 R12.2 U1.2 | length 271.9
  Top w10: C15.1@695,646.5 765,576.5 856.5,576.5 875.7,595.7 U1.2
NetC16_1: C16.1 U1.27 | length 140.4
  Top w10: U1.27@1368.17,659.92 1368.17,611.83 1393.5,586.5 C16.1@1393.5,530
NetC18_1: C18.1 R12.1 | length 70
  Top w10: C18.1@695,513.5 R12.1@765,513.5
NetC24_1: C24.1 R21.1 | length 76.4
  Bottom w10: R21.1@1095,1997.09 C24.1@1095,2073.5
NetC25_1: C25.1 J3.17 R27.1 | length 175.4
  Bottom w10: J3.17 428.5,350 458.5,320 C25.1@458.5,255
NetC26_1: C26.1 J3.15 R26.1 | length 163
  Bottom w10: J3.15 458.5,450 C26.1@458.5,385
NetC27_1: C27.1 J3.13 R25.1 | length 175.4
  Bottom w10: J3.13 428.5,550 458.5,580 C27.1@458.5,515
NetC38_1: C38.1 R47.1 U3.6 U3.7 | length 270.6
  Top w10: U3.7 U3.6 347.8,487.8 360,500 360,563.5 335,588.5 366.5,620 373.5,620 R47.1@405,651.5
NetD1_1: D1.1 R1.2 | length 115.6
  Top w10: D1.1 781.5,186.5 R1.2@895,186.5
NetD1_2: D1.2 Q1.3 | length 116
  Top w10: Q1.3 777.6,92.6 D1.2
NetD2_1: D2.1 R4.2 | length 115.6
  Top w10: R4.2@300,186.5 413.5,186.5 D2.1
NetD2_2: D2.2 Q2.3 | length 116
  Top w10: D2.2 417.4,92.6 Q2.3
NetD4_1: D4.1 R23.2 | length 105.6
  Top w10: D4.1 1065,2240 1078.5,2226.5 R23.2@1115,2226.5
NetD5_1: D5.1 R24.2 | length 91.8
  Top w10: D5.1 206.5,95 R24.2@235,123.5
NetJ3_14: J3.14 R16.1 | length 2182.7
  Top w10: v1(100,140) v1(100,500) ; R16.1@1655,148.5 1681.5,148.5 1700,130 v1(1700,70)
  Bottom w10: v1(100,140) 755,140 825,70 v1(1700,70) ; v1(100,500) 125,500 139.5,514.5 J3.14
NetQ3_4: Q3.4 R28.2 | length 382.3
  Top w10: R28.2@505,1481.5 505,1520 499,1526 499,1800 524,1825 Q3.4
NetQ4_4: Q4.4 R29.2 | length 380.9
  Top w10: R29.2@1055,1481.5 1055,1795 1085,1825 Q4.4
NetQ5_4: Q5.4 R30.2 | length 386.8
  Top w10: R30.2@1615,1481.5 1615,1805 1635,1825 Q5.4
NetQ6_4: Q6.4 R31.2 | length 105.6
  Top w10: Q6.4 980,1535 985,1530 R31.2@985,1481.5
NetQ7_4: Q7.4 R32.2 | length 105.6
  Top w10: Q7.4 1540,1530 1545,1525 R32.2@1545,1481.5
NetQ8_4: Q8.4 R33.2 | length 105.6
  Top w10: Q8.4 2100,1530 2105,1525 R33.2@2105,1481.5
NetR5_2: R5.2 U1.7 | length 228.8
  Top w10: R5.2@925,441.5 925,480 974.19,529.19 U1.7
NetR7_1: R7.1 R8.2 U1.3 | length 332.4
  Top w10: R8.2@695,441.5 765,441.5 895.39,571.89 U1.3
NetR10_1: R10.1 U1.4 | length 241.6
  Top w10: R10.1@835,441.5 835,480 915.09,560.09 U1.4
NetR11_2: R11.2 U1.1 | length 91.6
  Top w10: R11.2@765,648.5 766.42,649.92 U1.1
NetR27_2: R27.2 R43.2 U3.1 | length 284.1
  Top w10: U3.1 425,381.5 446.5,360 555,360 v1(575,340)
  Bottom w10: R27.2@521.5,320 555,320 v1(575,340)
NetR43_1: R43.1 R44.2 U3.2 | length 227.5
  Top w10: R43.1@383.5,360 383.5,448.5 397.2,462.2 U3.2 471.3,462.2 R44.2@503.5,430
NetR45_2: R45.2 R47.2 U3.3 | length 240.8
  Top w10: R47.2@405,588.5 380,563.5 380,500 392.2,487.8 U3.3 471.3,487.8 R45.2@503.5,520
NetR46_1: R46.1 R48.2 U3.5 | length 146.9
  Top w10: R46.1@240,441.5 240,513.5 U3.5@314.9,513.5
OC_ADJ/SCLK: R15.2 R16.2 R19.2 U1.11 | length 1406.6
  Top w10: v1(1010,170) 1020,180 1020,455 1053,488 1053,604.9 U1.11 ; R15.2@1585,283.5 1585,211.5 1655,211.5 1683.5,211.5 1700,195 v1(1700,170)
  Bottom w10: v1(1010,170) v1(1700,170)
PH: C10.1 D3.1 L1.2 U1.50 U1.51 | length 1154.4
  Top w10: D3.1 D3.1@397.99,801.23 ; C10.1@935,1141.5 935,1140 965,1110 965,1000 ; U1.51 954.49,989.49 965,1000 ; U1.50 974.19,990.81 965,1000
  Top w20: D3.1@397.99,801.23 475,878.23 L1.2 475,1080 v1(555,1160) ; C10.1@935,1141.5 v1(935,1205)
  Bottom w20: v1(555,1160) 655,1160 700,1205 v1(935,1205)
PWM_AH: J4.2 U1.17 | length 1935
  Top w10: U1.17 1171.19,604.91 1171.2,468.8 1245,395 v1(1245,245) ; v1(1770,245) v1(1770,1150)
  Bottom w10: v1(1245,245) v1(1770,245) ; v1(1770,1150) J4.2
PWM_AL: J4.4 U1.18 | length 1762.2
  Top w10: U1.18 1190.89,604.91 1190.9,479.1 1270,400 v1(1270,270) ; v1(1745,270) v1(1745,1050)
  Bottom w10: v1(1270,270) v1(1745,270) ; v1(1745,1050) J4.4
PWM_BH: J4.6 U1.19 | length 1589.4
  Top w10: U1.19 1210.59,604.91 1210.6,489.4 1295,405 v1(1295,295) ; v1(1720,295) v1(1720,950)
  Bottom w10: v1(1295,295) v1(1720,295) ; v1(1720,950) J4.6
PWM_BL: J4.8 U1.20 | length 1416.6
  Top w10: U1.20 1230.29,604.91 1230.3,499.7 1320,410 v1(1320,320) ; v1(1695,320) v1(1695,850)
  Bottom w10: v1(1320,320) v1(1695,320) ; v1(1695,850) J4.8
PWM_CH: J4.10 U1.21 | length 1243.8
  Top w10: U1.21 1249.99,604.91 1250,510 1345,415 v1(1345,345) ; v1(1670,345) v1(1670,750)
  Bottom w10: v1(1345,345) v1(1670,345) ; v1(1670,750) J4.10
PWM_CL: J4.12 U1.22 | length 1071
  Top w10: U1.22 1269.69,604.91 1269.7,520.3 1370,420 v1(1370,370) ; v1(1645,370) v1(1645,650)
  Bottom w10: v1(1370,370) v1(1645,370) ; v1(1645,650) J4.12
SH_A: C5.2 J11.3 Q3.1 Q3.2 Q3.3 Q6.5 R37.1 U1.46 | length 1837.1
  Top w10: Q3.3 Q3.2 Q3.1 ; Q6.5 745,1586.06 745,1425 845,1325 940,1325 1005,1260 1005,1231.5 1040,1196.5 1040,1085 1052.99,1072.01 U1.46
  Top w100: Q6.5 905.79,1770.59 J11.3
  Bottom w10: J11.3 1325,2080.2 R37.1@1325,2006.5
SH_B: C6.2 J11.2 Q4.1 Q4.2 Q4.3 Q7.5 R39.1 U1.41 | length 1659.6
  Top w10: U1.41 1151.49,1200.01 1120,1231.5 1147.69,1259.19 1147.69,1287.69 1160,1300 1250,1300 1270,1320 v1(1270,1355) ; Q4.3 Q4.2 Q4.1 ; v1(1270,1510) 1305,1545 1305,1586.06 Q7.5 Q7.5@1470.2,1751.26 ; J11.2@1465.79,2130.59 J11.2
  Top w100: Q7.5@1470.79,1746.85 J11.2@1470.79,2130.59
  Bottom w10: v1(1270,1355) v1(1270,1510) ; J11.2 1540,2065.2 R39.1@1540,2006.5
SH_C: C7.2 J11.1 Q5.1 Q5.2 Q5.3 Q8.5 R41.1 U1.36 | length 2229.9
  Top w10: C7.2@1225,1231.5 1226.5,1230 v1(1265,1230) 1265,1115 1249.99,1099.99 U1.36 ; Q5.3 Q5.2 Q5.1 ; v1(1820,1335) 1820,1505 1870,1555 1870,1591.06 Q8.5
  Top w100: J11.1 2025.79,1779.41 Q8.5
  Bottom w10: v1(1265,1230) 1320,1230 1330,1220 1425,1220 1500,1295 1780,1295 v1(1820,1335) ; J11.1 1755,2050.2 R41.1@1755,2006.5
SL_A: J5.1 Q6.1 Q6.2 Q6.3 R34.2 U1.44 | length 921.4
  Top w10: Q6.1 Q6.2 Q6.3 ; v1(1080,1275) 1080,1105 1092.4,1092.6 U1.44
  Bottom w10: 938,1387 938,1427 910,1455 R34.2 849.92,1375.08 945,1280 1075,1280 v1(1080,1275)
  other v1: 805,1420 780,1440 805,1460 775,1475 805,1495 775,1510
SL_B: J6.1 Q7.1 Q7.2 Q7.3 R35.2 U1.39 | length 944
  Top w10: U1.39 1190.89,1260.89 1205,1275 v1(1230,1275) ; Q7.1 Q7.2 Q7.3
  Bottom w10: v1(1230,1275) 1285,1275 1308.5,1251.5 1333.5,1251.5 1409.92,1327.92 R35.2 1470,1455 1498,1427 1498,1387
  other v1: 1360,1420 1330,1440 1360,1460 1325,1475 1360,1500 1325,1510
SL_C: J7.1 Q8.1 Q8.2 Q8.3 R36.2 U1.34 | length 1256.2
  Top w10: U1.34 1289.39,1079.39 1315,1105 v1(1315,1200) ; Q8.1 Q8.2 Q8.3
  Bottom w10: v1(1315,1200) 1435,1200 1510,1275 1820,1275 1914.92,1369.92 R36.2 1975,1455 2004,1426 2004,1387
  other v1: 1845,1400 1870,1420 1845,1440 1870,1460 1845,1480 1860,1510
VA_FB: C34.1 J3.7 R37.2 R38.2 U2.3 | length 3571.3
  Top w10: U2.3 133,732 152,713 228,713 275,760 275,825 v1(300,850)
  Bottom w10: C34.1@458.5,850 J3.7 v1(300,850) 250,900 250,1025 270,1045 270,1210 65,1415 65,2190 110,2235 1330,2235 1365,2200 1365,1983.5 1325,1943.5 R38.2@1255,1943.5
VB_FB: C35.1 J3.9 R39.2 R40.2 U2.4 | length 3872.4
  Top w10: U2.4 133,673 150,690 240,690 v1(300,750)
  Bottom w10: C35.1@458.5,750 J3.9 v1(300,750) 225,825 225,1030 250,1055 250,1200 45,1405 45,2200 100,2255 1525,2255 1580,2200 1580,1983.5 1540,1943.5 R40.2@1470,1943.5
VC_FB: C36.1 J3.11 R41.2 R42.2 U2.6 | length 4093.9
  Top w10: U2.6 v1(245,658)
  Bottom w10: C36.1@458.5,650 J3.11 253,650 200,703 200,1035 230,1065 230,1190 25,1395 25,2210 90,2275 1720,2275 1795,2200 1795,1983.5 1755,1943.5 R42.2@1685,1943.5
pads on no net: J3.1 J3.4 J3.10 J3.12 J3.16 J3.18 J3.19 J3.20 J4.5 J4.7 J4.9 J4.14 J4.16 J4.18 J4.19 J4.20 U1.55

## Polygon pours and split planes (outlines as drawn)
SL_C on Top "SL_C_Top" (solid, remove dead copper, pour order 50): 1935,1610 1935,1560 1900,1525 1860,1525 1835,1500 1835,1385 1945,1385 2065,1560 2065,1610
+3.3V on Top "+3.3V-Top" (solid, remove dead copper, pour order 40): 125,1000 125,1255 525,1255 525,1175 360,1175 185,1000
+PVDD on Top "PVDD-Top" (solid, remove dead copper, pour order 43): 180,1600 450,1600 450,1960 180,1960
+PVDD on Top "PVDD1_Top" (solid, remove dead copper, pour order 57): 675,1505 675,1470 895,1250 895,1021 920,984 920,921 890,921 890,983 845,1015 845,1235 620,1460 620,1505
+PVDD on Top "PVDD2_Top" (solid, remove dead copper, pour order 56): 1225,1455 1430,1250 1430,1017 1382,979 1382,921 1393,921 1480,991 1480,1260 1235,1505 1225,1505
SL_B on Top "SL_B_Top" (solid, remove dead copper, pour order 51): 1375,1610 1310,1525 1310,1445 1370,1385 1505,1385 1505,1610
SL_A on Top "SL_A_Top" (solid, remove dead copper, pour order 52): 815,1610 760,1555 760,1435 810,1385 945,1385 945,1610
+PVDD on Top "PVDDA_Top" (solid, remove dead copper, pour order 49): 520,1765 730,1765 730,1560 675,1505 675,1455 565,1455 565,1505 520,1550 520,1765
+PVDD on Top "PVDDB_Top" (solid, remove dead copper, pour order 48): 1080,1765 1290,1765 1290,1560 1235,1505 1235,1455 1125,1455 1125,1505 1080,1550 1080,1765
+PVDD on Top "PVDDC_Top" (solid, remove dead copper, pour order 47): 1640,1765 1850,1765 1850,1560 1795,1505 1795,1455 1685,1455 1685,1505 1640,1550 1640,1765
SH_A on Top "SH_A_Top" (solid, remove dead copper, pour order 42): 585,1865 585,1795 765,1795 805,1755 805,1645 1010,1645 1010,1805 1310,2105 1250,2180
SH_B on Top "SH_B_Top" (solid, remove dead copper, pour order 45): 1145,1865 1145,1790 1325,1790 1360,1755 1360,1645 1570,1645 1570,1865 1520,2140 1435,2165
SH_C on Top "SH_C_Top" (solid, remove dead copper, pour order 46): 1705,1865 1705,1790 1885,1790 1920,1755 1920,1645 2130,1645 2130,1865 1700,2175 1620,2130
GND on Top "GND_TOP" (solid, remove dead copper, pour order 58): 0,2300 2200,2300 2200,-100 0,-100
SL_C on Bottom "SL_C_Bot" (solid, remove dead copper, pour order 53): 1860,1525 1945,1525 1945,1385 1835,1385 1835,1500
+3.3V on Bottom "+3.3V-Bot" (solid, remove dead copper, pour order 44): 100,1170 215,1170 215,1090 190,1090 150,1130 100,1130
+PVDD on Bottom "PVDD_Bot" (solid, remove dead copper, pour order 41): 1850,1875 1850,1600 180,1600 180,1960 650,1960 725,2065 725,2170 925,2170 925,2065 1115,1875
SL_B on Bottom "SL_B_Bot" (solid, remove dead copper, pour order 54): 1310,1525 1440,1525 1440,1385 1370,1385 1310,1445
SL_A on Bottom "SL_A_Bot" (solid, remove dead copper, pour order 55): 760,1525 880,1525 880,1385 810,1385 760,1435
GND on Bottom "GND_BOT" (solid, remove dead copper, pour order 59): 0,0 0,2300 2200,2300 2200,0

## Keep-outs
Keep-Out Layer:
  the board outline again, w10

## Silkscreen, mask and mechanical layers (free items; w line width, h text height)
Silkscreen Top:
  lines w7: 820,605 1430,605 1430,995 820,995 820,605
  lines w10: 80,1035 110,1035 ; 95,1020 95,1050 ; 135,1800 165,1800 ; 150,1785 150,1815 ; 305,1760 335,1760 ; 320,1745 320,1775
  text "PVDD" at 1005,2020 h30
  text "GND" at 535,1870 h50
  text "A" at 1250,1870 h50
  text "PVDD" at 740,1865 h50
  text "B" at 1455,1865 h50
  text "C" at 1650,1865 h50
  text "Motor Drive BoosterPack" at 2035,900 h40 r270
  text "BOOSTXL-DRV8301 REVB" at 2130,900 h40 r270
  text "DRV8301" at 965,540 h50
  text "+3.3V" at 90,20 h30
  text "FAULT" at 355,20 h30
  text "OCTW" at 720,20 h30
M1 Board Outline:
  the board outline again, w10
Drill Drawing:
  lines w1: 0,1970 0.03,1970 ; 0,2270 0.03,2270
  text "Drill Table" at 2750,2100 h60
  text ".Legend" at 2692,1126 h60

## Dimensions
0,0 to 0,2300 on M2 Dimensions
0,2300 to 2200,2300 on M2 Dimensions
